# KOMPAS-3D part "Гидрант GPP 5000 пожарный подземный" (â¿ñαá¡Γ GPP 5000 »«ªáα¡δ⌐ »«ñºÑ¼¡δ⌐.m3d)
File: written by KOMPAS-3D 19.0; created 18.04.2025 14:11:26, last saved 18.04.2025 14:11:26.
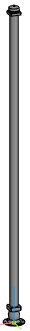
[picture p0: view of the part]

Document properties: Полное имя файла: E:\Dendor Работа Сачек\3D для проекитирвщиков\11.1 Тип GPP. Гидрант пожарный подземный\stp_Тип GPP. 750-6000 Гидрант пожарный подземный\Гидрант GPP 5000 пожарный подземный.m3d

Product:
- Part/product: Гидрант GPP 5000 пожарный подземный

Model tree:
1. Операция без истории:1  (labels: Гидрант GPP 5000 пожарный подземный)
